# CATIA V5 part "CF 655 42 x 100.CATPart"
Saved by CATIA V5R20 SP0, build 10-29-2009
Part number: CF 655 42 x 100
Definition: NONE
Nomenclature: CF 655 42 x 100
Source: Unknown
Description: CF 655 42 x 100
Bounding box of the stored display mesh (mm): x -70 to 30, y -31.5 to 31.5, z -31.5 to 31.5
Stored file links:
  C:\Users\Utente\Desktop\IO LAVORO\3D X SITO CF\X SITO\CF 655\CF 655 42 x 100.CATPart
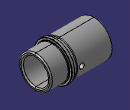
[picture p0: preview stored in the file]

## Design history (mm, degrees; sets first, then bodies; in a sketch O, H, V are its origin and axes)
Body1 "CF 655 42 x 100" (main body)
  Solid1: solid without history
